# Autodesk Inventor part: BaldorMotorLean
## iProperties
Shininess: 64.0
Length Units: 11272
Angle Units: 11279
Time Units: 11290
Mass Units: 11286
Length Display Precision: 3
Angle Display Precision: 2
Compacted: True
Part Number: BaldorMotorLean
Document SubType Name: Modeling
Created: 2003-11
Designer: Larry Caldwell
Material: Steel CRS
Manufacturer: Standard
Standards Organization: Custom
Description: 3/4 Hp 56C
Density: 7.86 g/cm^3
Mass: 56758.6 g
Surface Area: 2793.81 cm^2
Volume: 7221.2 cm^3
Density: 0.0
Volumn: 0.0
Area: 0.0
PropertySet Name: Model Information
Control State: 0
Master: False
Checked Out: False
d55: 0,060 in
SaveDate: 2003-11-22
SaveTime: 10:54
TotalMass: 125.145 lbmass
TotalVolume: 440.714 in^3
Author: Larry Caldwell
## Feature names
1. Revolution1
2. Revolution2
3. Fillet1
4. Extrusion2
5. Fillet2
6. Extrusion3
7. Extrusion4
8. Extrusion5
9. Fillet3
10. Fillet4
11. Extrusion6
12. Extrusion7
13. Extrusion8
14. Fillet5
15. Fillet6
16. Extrusion9
17. Extrusion10
18. Fillet7
19. Fillet8
20. Extrusion11
21. Hole1
